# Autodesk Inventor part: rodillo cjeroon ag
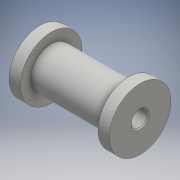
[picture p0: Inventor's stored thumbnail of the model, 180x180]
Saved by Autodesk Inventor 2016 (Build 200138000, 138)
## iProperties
Created: 2016-06
Part Number: rodillo cjeroon ag
Material: Genérico
Document SubType Name: Modeling
Designer: adm
Density: 1 g/cm^3
Appearance: Valor por defecto
Author: adm
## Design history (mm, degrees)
sketch "Boceto1"
  geometry: L1 (0, 0)-(0, 13.5); L2 (0, 13.5)-(5, 13.5); L3 (5, 13.5)-(5, 9); L4 (5, 9)-(39, 9); L5 (39, 9)-(39, 13.5); L6 (39, 13.5)-(44, 13.5); L7 (0, 0)-(44, 0); L8 (44, 0)-(44, 13.5)
  constraints: 16 end point, 5 perpendicular, 2 vertical, 1 horizontal, 1 horizontal alignment
  dimensions: "d0" = 44 distance of L1.start L7.end; "d1" = 5 distance of L1.end L2.end; "d2" = 5 distance of L5.end L6.end; "d3" = 13.5 distance between parallel lines of L7 L2; "d4" = 9 distance between parallel lines of L7 L4
revolve "Revolución1" sketch "Boceto1" stored, may be unused: angle "d5" = 90 deg
sketch "Boceto2"
  geometry: C1 r 3.5 at (0, 0); 1 further point
  constraints: 1 centre point, 1 coincident
  dimensions: "d6" = 7 diameter of C1
extrude "Extrusión1" cut sketch "Boceto2" stored distance "d7" = 10; taper "d8" = 0 deg
node "Plano de trabajo1"
sketch "Boceto3"
  geometry: L1 (0, 13.5)-(0, -13.5) reference; L2 (-44, 13.5)-(-44, -13.5) reference; C1 r 1 at (-34, 0); C2 r 1 at (-10, 0); 2 further points
  constraints: 2 centre point
  dimensions: "d10" = 2 diameter of C1; "d11" = 2 diameter of C2; "d12" = 10 distance from line of C2.centre L1
extrude "Extrusión2" cut sketch "Boceto3" distance "d14" = 10; taper "d15" = 0 deg
chamfer "Chaflán1" distance "d16" = 0.5; stored, may be unused: second distance "d17" = 2, angle "d18" = 45 deg
node "Sólido1"
other parameters: "d9" = 9
